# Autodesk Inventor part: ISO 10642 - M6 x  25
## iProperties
Comments: To add or edit properties for Autodesk Inventor files, use iProperties.
Created: 2005-06
Part Number: ISO 10642 - M6 x  25
Vendor: Autodesk Inc.
Document SubType Name: Modeling
Designer: John Blackburn
Material: Default
Description: Hexagon Socket Countersunk Head Screw
Standard: ISO 10642
Size Designation: M6 x  25
Alert: To add or edit properties for Autodesk Inventor files, use iProperties.
Control State: 0
Master: False
Checked Out: False
Shininess: 64.0
Length Units: 11269
Angle Units: 11279
Time Units: 11290
Mass Units: 11283
Length Display Precision: 3
Angle Display Precision: 2
Compacted: True
EGR: 1
Density: 0.0
Volumn: 0.0
Area: 0.0
PropertySet Name: Model Information
Author: John Blackburn
Revision Number: 8
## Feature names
1. Body [Revolution]
2. Slot [Extrusion]
3. Chamfer1
